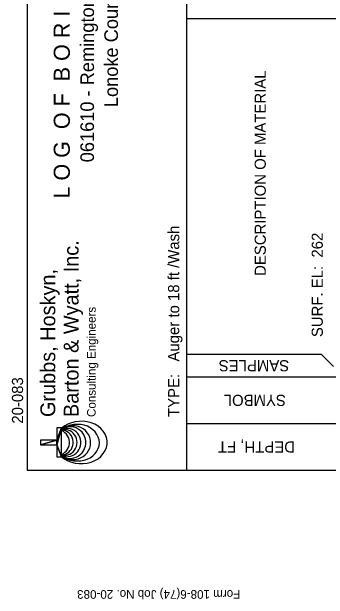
# Model space of a CAD drawing. Extents: x 1313964 to 1316843, y 2087046 to 2096619.
# Drawn here: x 1313974.69 to 1313989.13, y 2089812.81 to 2089839.64 of the extents above; entities that cross this region are included whole.
import ezdxf

# ---------------------------------------------------------------- set-up
doc = ezdxf.new("R2010")
doc.units = 0
doc.layers.add('B-Sub-Contour', color=7, linetype='Continuous')
doc.layers.add('Default', color=7, linetype='Continuous')

# ---------------------------------------------------------------- blocks, each defined once
blk = doc.blocks.new('DGRFC_GGHLOGO')
at = {"layer": 'Default'}
for points in [[(371581.68, 791230.32), (371581.68, 1050310.32), (295381.68, 1050310.32), (371581.68, 791230.32)], [(371581.68, 791230.32), (295381.68, 1050310.32), (295381.68, 791230.32), (371581.68, 791230.32)], [(295381.68, 791230.32), (104881.68, 791230.32), (104881.68, 715030.32), (295381.68, 791230.32)], [(295381.68, 791230.32), (104881.68, 715030.32), (562081.68, 715030.32), (295381.68, 791230.32)], [(295381.68, 791230.32), (562081.68, 715030.32), (371581.68, 791230.32), (295381.68, 791230.32)], [(562081.68, 715030.32), (562081.68, 791230.32), (371581.68, 791230.32), (562081.68, 715030.32)]]:
    blk.add_lwpolyline(points, close=True, dxfattribs=at)
for points in [[(105216.96, 715030.32), (100004.88, 709757.28), (68915.28, 666170.88), (42854.88, 615848.4), (22494.24, 560009.04), (8351.52, 500115.84), (792.48, 437662.32), (0, 374202.96), (7802.88, 311353.2), (23439.12, 250698), (46847.76, 193791.84), (77510.64, 142006.32), (114635.28, 96713.04), (157246.32, 59039.76), (204337.92, 29900.88), (254660.4, 10058.4), (306994.56, 0), (359968.8, 0), (412302.96, 10058.4), (462625.44, 29900.88), (509717.04, 59039.76), (552328.08, 96713.04), (589452.72, 142006.32), (620115.6, 193791.84), (643524.24, 250698), (659160.48, 311353.2), (666963.36, 374202.96), (666170.88, 437662.32), (658611.84, 500115.84), (644469.12, 560009.04), (624108.48, 615848.4), (598048.08, 666170.88), (566958.48, 709757.28), (561746.4, 715030.32)], [(111587.28, 715030.32), (108691.68, 711311.76), (85770.72, 670895.28), (67177.92, 625266.72), (53400.96, 575584.32), (44744.64, 523097.76), (41422.32, 469087.2), (42702.48, 414924.24), (52760.88, 362010.96), (69738.24, 311597.04), (93238.32, 264993.12), (122651.52, 223387.92), (157246.32, 187756.8), (196169.28, 159075.12), (238414.56, 137982.96), (282976.32, 125089.92), (328665.84, 120639.84), (374385.84, 124815.6), (419008.56, 137464.8), (461345.28, 158282.64), (500390.16, 186720.48), (535137.36, 222138.24), (564733.44, 263591.04), (588416.4, 310042.56), (605637.6, 360334.56), (615909.36, 413217.36), (618195.36, 467349.84), (615055.92, 521360.4), (606582.48, 573938.4), (592927.44, 623742.72), (574487.04, 669523.68), (551718.48, 710123.04), (547908.48, 715030.32)], [(113477.04, 715030.32), (111434.88, 712226.16), (91531.44, 674613.84), (76748.64, 633618.24), (67421.76, 590275.68), (63825.12, 545683.44), (65227.2, 500969.28), (74462.64, 457260.96), (90098.88, 415625.28), (111770.16, 377098.56), (138927.84, 342717.12), (170870.88, 313273.44), (206837.28, 289560), (245882.16, 272155.92), (287030.16, 261457.44), (329031.6, 257799.84), (371520.72, 261244.08), (412729.68, 271698.72), (451866, 288889.44), (487923.84, 312420), (520019.28, 341680.8), (547329.36, 375940.32), (569183.52, 414314.64), (585033.12, 455889.36), (594451.44, 499567.2), (596463.12, 544250.88), (593049.36, 588873.6), (583905.36, 632246.64), (569305.44, 673333.68), (549554.4, 711067.92), (546658.8, 715030.32)], [(117957.6, 715030.32), (116220.24, 712561.44), (98968.56, 677509.44), (87386.16, 640201.92), (81747.36, 601522.8), (82174.08, 562477.92), (88696.8, 523951.2), (101071.68, 486887.52), (119085.36, 452231.76), (142250.16, 420776.4), (170047.92, 393283.44), (201747.12, 370453.92), (236616.24, 352836.48), (273801.84, 340857.84), (312389.52, 334792.32), (351464.88, 334792.32), (390052.56, 340857.84), (427238.16, 352836.48), (462107.28, 370453.92), (493806.48, 393283.44), (521573.76, 420776.4), (544769.04, 452231.76), (562752.24, 486887.52), (575157.6, 523951.2), (581649.84, 562477.92), (582076.56, 601522.8), (576437.76, 640201.92), (564855.36, 677509.44), (547634.16, 712561.44), (545896.8, 715030.32)], [(124632.72, 715030.32), (123809.76, 713353.92), (113934.24, 680252.64), (109301.28, 646023.6), (110002.32, 611459.28), (116006.88, 577443.6), (127223.52, 544769.04), (143316.96, 514228.08), (163982.4, 486521.76), (188640.72, 462351.12), (216743.28, 442264.8), (247619.52, 426780.96), (280507.44, 416234.88), (314645.04, 410900.88), (349209.36, 410900.88), (383316.48, 416234.88), (416234.88, 426780.96), (447080.64, 442264.8), (475213.68, 462351.12), (499872, 486521.76), (520506.96, 514228.08), (536630.88, 544769.04), (547847.52, 577443.6), (553852.08, 611459.28), (554553.12, 646023.6), (549920.16, 680252.64), (540014.16, 713353.92), (539221.68, 715030.32)], [(130972.56, 715030.32), (130454.4, 713079.6), (127284.48, 680740.32), (129235.2, 648309.6), (136306.56, 616579.92), (148254.72, 586343.76), (164805.36, 558393.6), (185562.24, 533400), (210007.2, 511972.56), (237530.64, 494659.92), (267401.04, 481919.28), (298917.36, 474024.96), (331317.6, 471190.32), (363717.84, 473506.8), (395356.08, 480882.96), (425470.32, 493166.4), (453237.6, 510021.84), (478017.84, 531053.04), (499170.96, 555711.36), (516178.8, 583417.68), (528614.64, 613440.48), (536173.68, 645048.24), (538642.56, 677448.48), (535990.8, 709818.24), (534710.64, 715030.32)], [(135483.6, 715030.32), (135483.6, 714420.72), (140482.32, 683727.36), (150174.96, 654192.24), (164378.64, 626546.88), (182727.6, 601431.36), (204764.64, 579485.76), (229941.12, 561258.72), (257647.44, 547176.96), (287243.52, 537606.24), (317936.88, 532759.92), (349026.48, 532759.92), (379719.84, 537606.24), (409315.92, 547176.96), (437022.24, 561258.72), (462198.72, 579485.76), (484235.76, 601431.36), (502584.72, 626546.88), (516788.4, 654192.24), (526481.04, 683727.36), (531479.76, 714420.72), (531479.76, 715030.32)], [(146151.6, 715030.32), (160690.56, 687811.68), (179679.6, 662574.24), (202326.24, 640567.68), (228112.32, 622279.68), (256367.28, 608167.44), (286481.52, 598566.24), (317693.04, 593719.92), (349270.32, 593719.92), (380481.84, 598566.24), (410596.08, 608167.44), (438851.04, 622279.68), (464637.12, 640567.68), (487283.76, 662574.24), (506272.8, 687811.68), (520811.76, 715030.32)]]:
    blk.add_lwpolyline(points, dxfattribs=at)

msp = doc.modelspace()

# ---------------------------------------------------------------- linework, layer by layer
at = {"layer": 'B-Sub-Contour'}
for points in [[(1314036.804, 2089818.705), (1314036.804, 2089861.576), (1313975.385, 2089861.576), (1313975.385, 2089818.705), (1314036.804, 2089818.705)], [(1313982.683, 2089818.705), (1313982.683, 2089861.576)], [(1314034.372, 2089839.319), (1313982.683, 2089839.319)], [(1313988.824, 2089823.995), (1313982.683, 2089823.995)], [(1313989.372, 2089823.448), (1313988.824, 2089823.995)], [(1314034.372, 2089822.961), (1313982.683, 2089822.961)], [(1314034.372, 2089820.833), (1313982.683, 2089820.833)]]:
    msp.add_lwpolyline(points, dxfattribs=at)

# ---------------------------------------------------------------- block references
at = {"layer": 'B-Sub-Contour', "xscale": 2.894891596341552e-06, "yscale": 2.894891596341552e-06, "rotation": 90}
msp.add_blockref('DGRFC_GGHLOGO', (1313979.034, 2089819.009), dxfattribs=at)

# ---------------------------------------------------------------- texts
at = {"layer": 'B-Sub-Contour'}
for s, height, rotation, p in [('L O G  O F  B O R I N G  N O.  S1', 0.7352, 90, (1313977.337, 2089831.115)), ('061610 - Remington Road over I-40', 0.62209, 90, (1313978.44, 2089832.77)), ('Lonoke County, Arkansas', 0.62209, 90, (1313979.534, 2089835.288)), ('DESCRIPTION OF MATERIAL', 0.50899, 90, (1313986.282, 2089827.583)), ('TYPE:   Auger to 18 ft /Wash', 0.50899, 90, (1313982.329, 2089821.137)), ('SURF. EL:  262', 0.50899, 90, (1313988.885, 2089824.786)), ('Barton & Wyatt, Inc.', 0.67865, 90, (1313977.736, 2089821.137)), ('Grubbs, Hoskyn,', 0.67865, 90, (1313976.672, 2089821.137)), ('Consulting Engineers', 0.39588, 90, (1313978.518, 2089821.137)), ('SAMPLES', 0.509, 180, (1313987.35, 2089823.733)), ('20-083', 0.509, 90, (1313975.203, 2089820.833)), ('SYMBOL', 0.509, 180, (1313987.199, 2089822.152)), ('DEPTH, FT', 0.509, 180, (1313987.615, 2089820.023)), ('Form 108-6(74) Job No. 20-083', 0.39588, 180, (1313985.115, 2089813.232))]:
    msp.add_text(s, height=height, rotation=rotation, dxfattribs=at).set_placement(p)

doc.saveas('drawing.dxf')
